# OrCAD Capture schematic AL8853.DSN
size Custom; title: AL8853,HIGH PERFORMANCE BOOST LED CONTROLLER; rev: 1.0; note: DS42211 Rev. 1 - 2
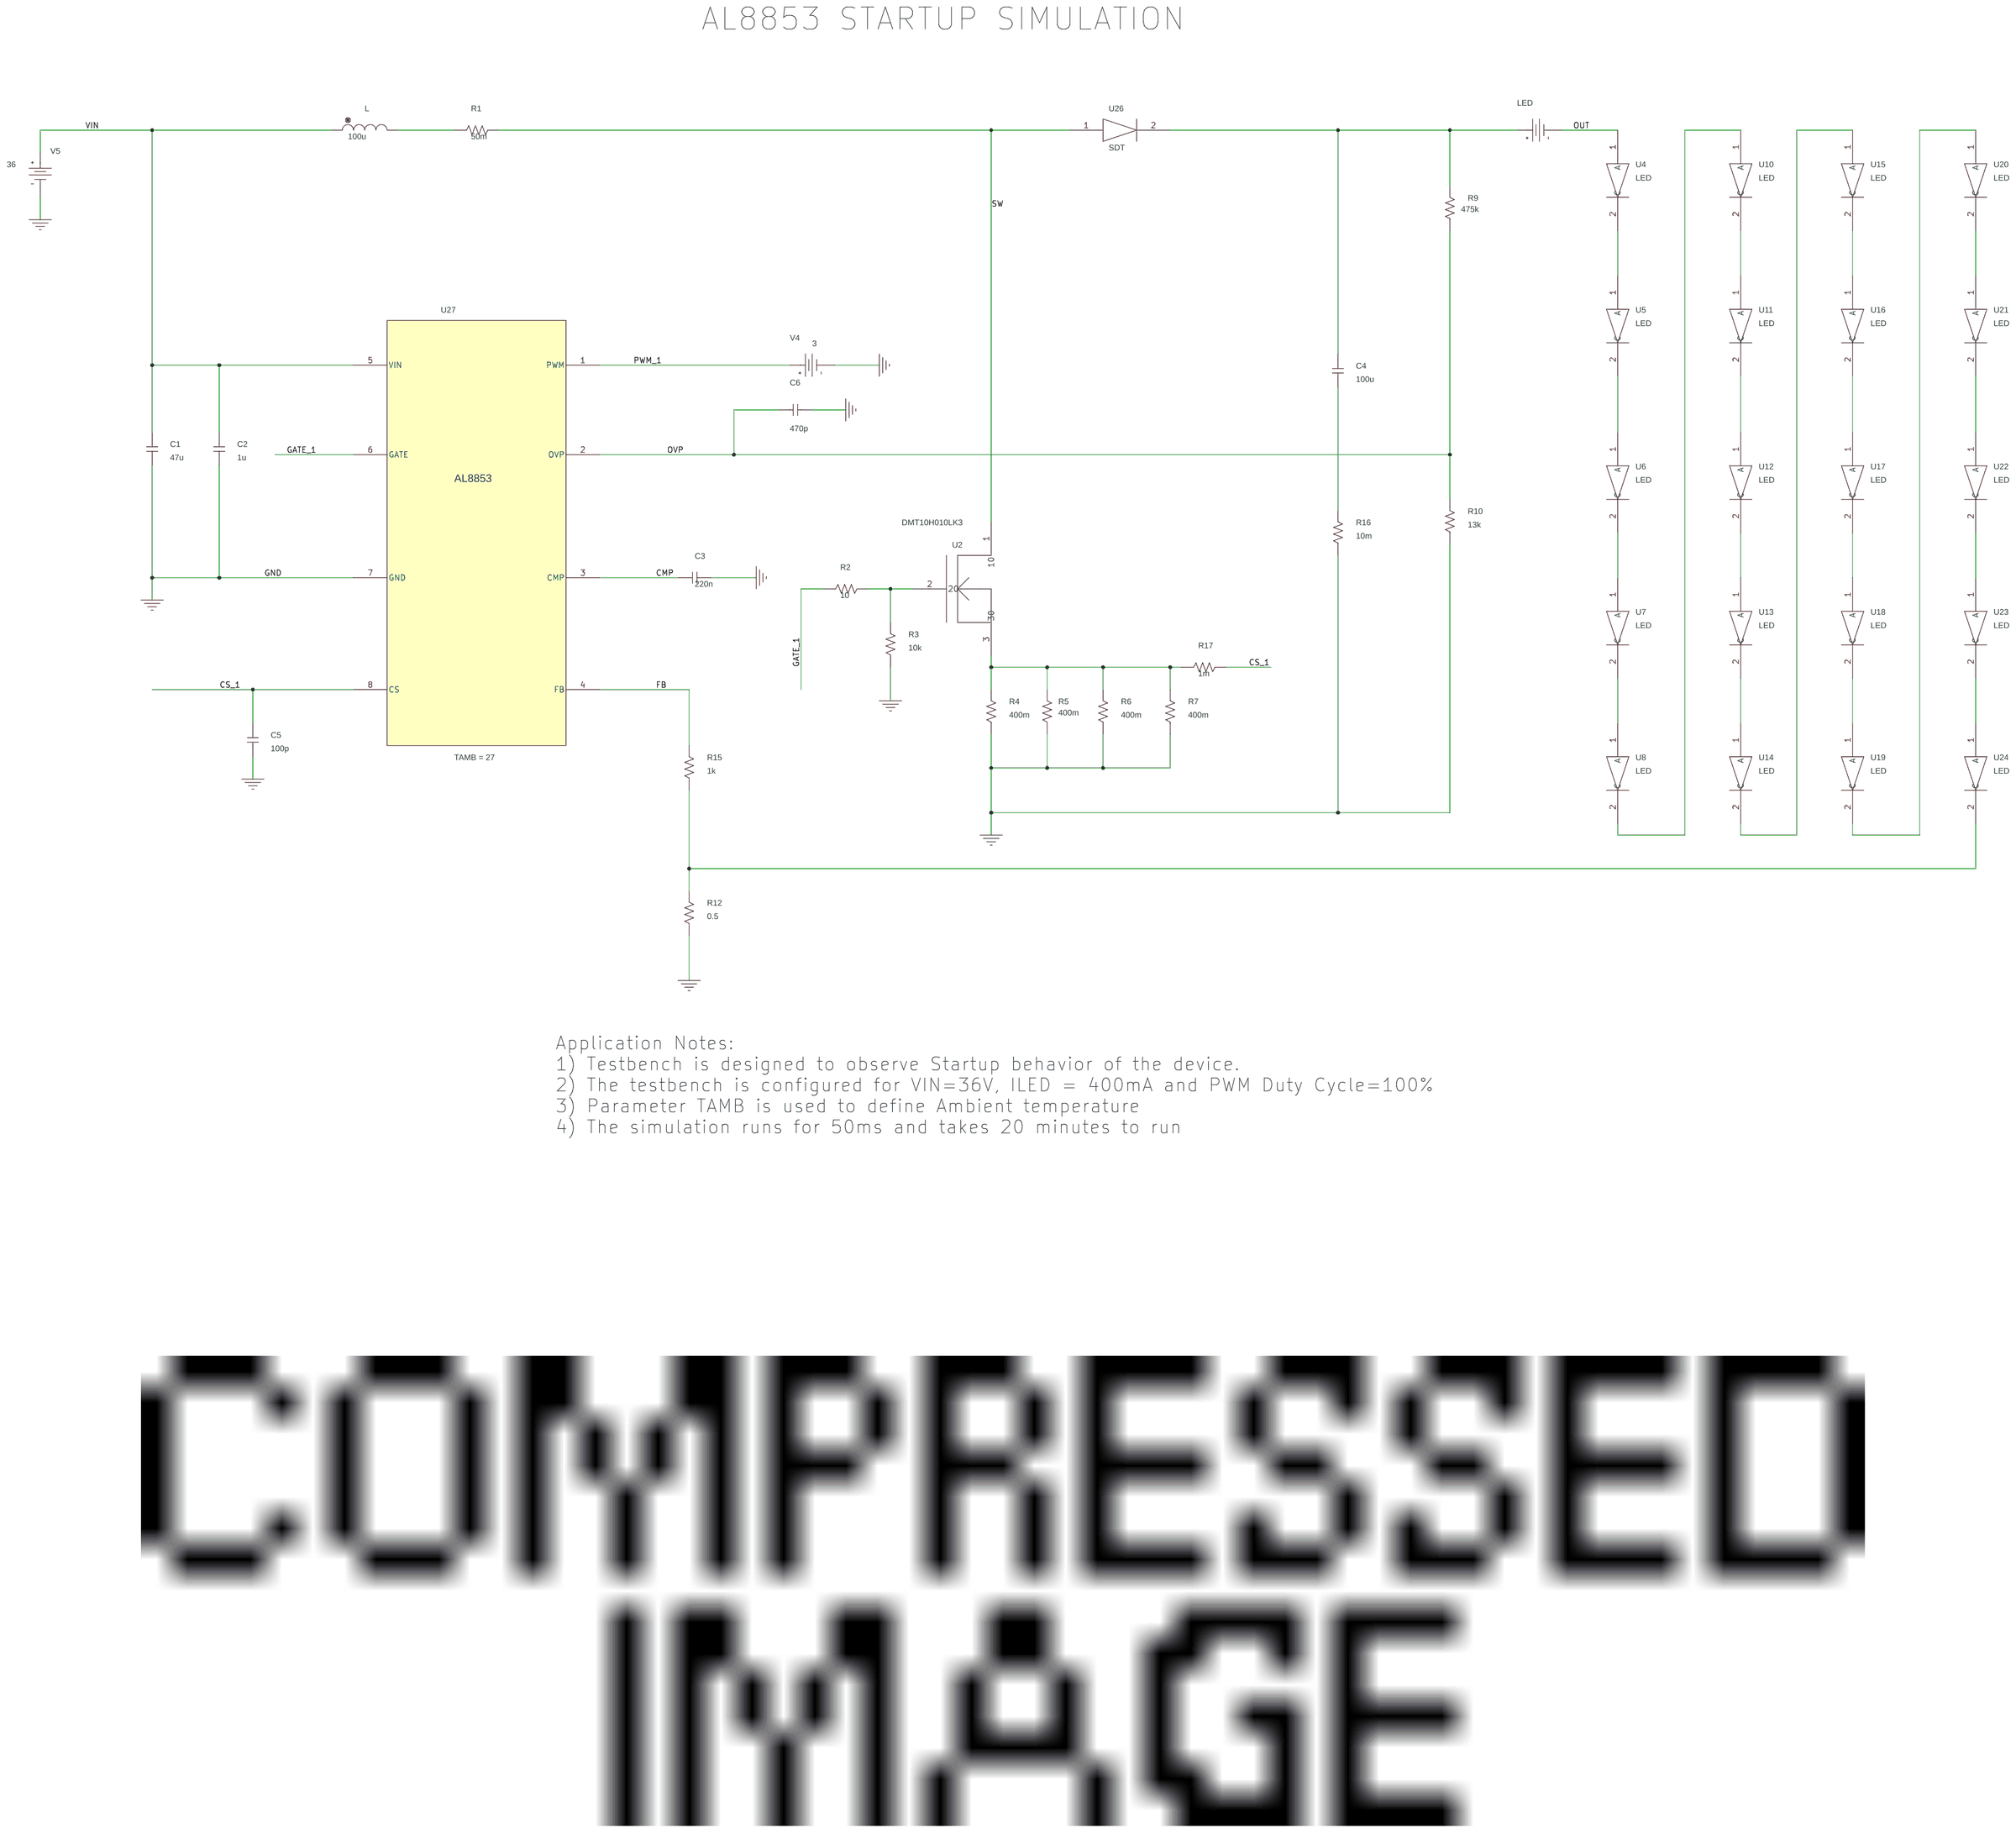
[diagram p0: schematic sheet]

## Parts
C1  47u  [RAD/CK05]
C2  1u  [RAD/CK05]
C3  220n  [RAD/CK05]
C4  100u  [RAD/CK05]
C5  100p  [RAD/CK05]
C6  470p  [RAD/CK05]
L  100u  [DISC/.350x.175/LS.200x.100/.034]
LED  VDC
R1  50m  [AX/RC05]
R2  10  [AX/RC05]
R3  10k  [AX/RC05]
R4  400m  [AX/RC05]
R5  400m  [AX/RC05]
R6  400m  [AX/RC05]
R7  400m  [AX/RC05]
R9  475k  [AX/RC05]
R10  13k  [AX/RC05]
R12  0.5  [AX/RC05]
R15  1k  [AX/RC05]
R16  10m  [AX/RC05]
R17  1m  [AX/RC05]
U2  DMT10H010LK3
U4  LED
U5  LED
U6  LED
U7  LED
U8  LED
U10  LED
U11  LED
U12  LED
U13  LED
U14  LED
U15  LED
U16  LED
U17  LED
U18  LED
U19  LED
U20  LED
U21  LED
U22  LED
U23  LED
U24  LED
U26  SDT
U27  AL8853
V4  VDC
V5  VDC

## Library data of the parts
C1-C6 = C
L = L
LED = VDC
R1-R7 R9 R10 R12 R15-R17 = R
U2 = DMT10H010LK3_0
U4-U8 U10-U24 = LED_0
U26 = SDT_0
U27 = AL8853_3: TAMB: 27
V4 = VDC: DC: 3
V5 = VDC: DC: 36

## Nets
VIN: C1.2 C2.2 L.1 U27.5(VIN) V5.0(+)
0: C1.1 C2.1 C3.2 C5.1 C6.1 R3.1 R4.1 R5.1 R6.1 R7.1 R10.1 R12.1 R16.1 U27.7(GND) V4.1(-) V5.1(-)
CMP: C3.1 U27.3(CMP)
CS_1: C5.2 R17.2 U27.8(CS)
FB: R15.2 U27.4(FB)
GATE_1: R2.1 U27.6(GATE)
OUT: LED.1(-) U4.1(A)
OVP: C6.2 R9.1 R10.2 U27.2(OVP)
PWM_1: U27.1(PWM) V4.0(+)
SW: R1.2 U2.1(10) U26.1
N70953: L.2 R1.1
N71023: R2.2 R3.2 U2.2(20)
N71131: R4.2 R5.2 R6.2 R7.2 R17.1 U2.3(30)
N71305: C4.2 LED.0(+) R9.2 U26.2
N71497: U7.2(C) U8.1(A)
N71503: U6.2(C) U7.1(A)
N71509: U5.2(C) U6.1(A)
N71515: U4.2(C) U5.1(A)
N71527: C4.1 R16.2
N71673: U13.2(C) U14.1(A)
N71679: U12.2(C) U13.1(A)
N71685: U11.2(C) U12.1(A)
N71691: U10.2(C) U11.1(A)
N71697: U14.2(C) U15.1(A)
N71701: U8.2(C) U10.1(A)
N71845: R12.2 R15.1 U24.2(C)
N71849: U18.2(C) U19.1(A)
N71855: U17.2(C) U18.1(A)
N71861: U16.2(C) U17.1(A)
N71867: U15.2(C) U16.1(A)
N71873: U19.2(C) U20.1(A)
N72035: U23.2(C) U24.1(A)
N72041: U22.2(C) U23.1(A)
N72047: U21.2(C) U22.1(A)
N72053: U20.2(C) U21.1(A)

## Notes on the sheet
- AL8853 STARTUP SIMULATION
- Application Notes:
  1) Testbench is designed to observe Startup behavior of the device.
  2) The testbench is configured for VIN=36V, ILED = 400mA and PWM Duty Cycle=100%
  3) Parameter TAMB is used to define Ambient temperature
  4) The simulation runs for 50ms and takes 20 minutes to run
